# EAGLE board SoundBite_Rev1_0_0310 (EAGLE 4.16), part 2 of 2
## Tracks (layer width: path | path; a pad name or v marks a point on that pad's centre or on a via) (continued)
MISO/SDA  (via drill 0.6) (continued)
  Bottom 0.254: v82.04,25.53 82.04,25.91 80.39,27.56 80.39,39.75 78.87,41.27 78.87,41.66 79.88,42.67 79.88,44.58 78.49,45.97 v78.49,46.99 | v40.77,11.05 38.35,11.05 36.2,13.21 36.2,18.67 39.88,22.35 39.88,22.99 v42.29,25.4 42.29,27.69 44.83,30.23 44.83,62.87 46.48,64.52 v46.48,65.28 | v43.81,74.17 42.67,75.31 42.67,86.23 40.77,88.14 35.43,88.14 34.92,88.65 SW2.8
  pour Bottom (isolate 0.508, rank 2, no thermals): 34.04,90.42 34.04,92.33 arc-90 34.92,93.22 arc-90 35.81,92.33 35.81,90.42 arc-90 34.92,89.53 arc-90
MODA  (via drill 0.6)
  Top 0.254: v49.78,65.41 49.78,67.56 46.23,71.12 46.23,75.44 46.99,76.2 46.99,83.06 47.75,83.82 47.75,93.47 45.09,96.14 45.09,97.28
  Top 0.381: U1.51 64.83,52.01 64.26,52.58 v64.26,52.83
  Top 1.27: 45.09,97.28 SW2.1
  Bottom 0.254: v64.26,52.83 63.5,53.59 63.5,57.78 62.48,58.8 56.01,58.8 53.34,61.47 52.32,61.47 49.78,64.01 v49.78,65.41
  pour Bottom (isolate 0.254, rank 2, no thermals): 45.97,100.58 arc90 45.47,101.09 44.7,101.09 arc90 44.2,100.58 44.2,98.3 arc90 44.7,97.79 45.47,97.79 arc90 45.97,98.3
MODB  (via drill 0.6)
  Top 0.254: v50.67,64.52 49.4,64.52 48.9,65.02 48.9,67.69 45.72,70.87 45.72,75.69 46.48,76.45 46.48,83.31 47.24,84.07 47.24,93.22 44.7,95.76 44.07,95.76 42.55,97.28
  Top 0.381: v64.39,54.23 64.39,54.04 65.48,52.95 U1.50
  Top 1.27: 42.55,97.28 SW2.2
  Bottom 0.254: v64.39,54.23 64.39,57.66 62.74,59.31 56.26,59.31 53.59,61.98 52.58,61.98 50.67,63.88 v50.67,64.52
  pour Bottom (isolate 0.254, rank 2, no thermals): 42.16,97.79 arc-90 41.66,98.3 41.66,100.58 arc-90 42.16,101.09 42.93,101.09 arc-90 43.43,100.58 43.43,98.3 arc-90 42.93,97.79
MODC  (via drill 0.6)
  Top 0.254: v51.56,65.41 51.56,64.01 51.05,63.5 49.66,63.5 48.39,64.77 48.39,67.44 45.21,70.61 45.21,75.95 45.97,76.71 45.97,83.57 46.74,84.33 46.74,92.96 44.45,95.25 42.04,95.25 40.01,97.28
  Top 0.381: U1.49 66.13,53.76 v65.66,54.23
  Top 1.27: 40.01,97.28 SW2.3
  Bottom 0.254: v65.66,54.23 65.02,54.86 65.02,57.78 62.99,59.82 56.52,59.82 53.85,62.48 52.83,62.48 51.56,63.75 v51.56,65.41
  pour Bottom (isolate 0.254, rank 2, no thermals): 39.62,97.79 arc-90 39.12,98.3 39.12,100.58 arc-90 39.62,101.09 40.39,101.09 arc-90 40.89,100.58 40.89,98.3 arc-90 40.39,97.79
MODD  (via drill 0.6)
  Top 0.254: v52.45,64.39 52.45,63.63 51.82,62.99 49.4,62.99 47.88,64.52 47.88,67.18 44.7,70.36 44.7,76.2 45.47,76.96 45.47,83.82 46.23,84.58 46.23,92.71 44.2,94.74 40.01,94.74 37.47,97.28
  Top 0.381: U1.48 66.78,54.51 65.91,55.37 v65.91,55.5
  Top 1.27: 37.47,97.28 SW2.4
  Bottom 0.254: v65.91,55.5 65.91,57.78 63.37,60.33 56.77,60.33 54.1,62.99 53.09,62.99 52.45,63.63 v52.45,64.39
  pour Bottom (isolate 0.254, rank 2, no thermals): 37.08,97.79 arc-90 36.58,98.3 36.58,100.58 arc-90 37.08,101.09 37.85,101.09 arc-90 38.35,100.58 38.35,98.3 arc-90 37.85,97.79
MOSI  (via drill 0.6)
  Top 0.254: U1.34 76.32,45.07 77.34,46.1 v79.76,46.1 | v17.4,9.02 16.51,8.13 16.51,3.68 17.27,2.92 R63.2 | v41.78,6.35 41.78,9.91 42.16,10.29 42.16,13.97 50.04,21.84 81.41,21.84 v84.2,24.64
  Top 1.016: v17.4,9.02 R114.P$1
  Bottom 0.254: v17.4,9.02 20.45,5.97 41.4,5.97 v41.78,6.35 | v79.76,46.1 80.39,45.47 80.39,43.18 81.41,42.16 81.41,28.7 84.2,25.91 v84.2,24.64
N$1
  Top 0.381: U5.40 88.48,46.19 R22.2
N$2
  Top 0.254: 43.56,47.12 R20.1
  Top 0.508: U12.1 43.56,47.12 | Q1.1 38.35,54.86 C30.1
  Top 1.27: R20.1 43.43,49.78 Q1.1
N$3
  Top 1.016: C31.1 R21.1
  Top 1.27: R21.1 37.59,50.8 Q1.2
N$4
  Top 0.508: U12.2 42.29,46.35 41.78,46.86 41.78,47.12 R20.2 41.02,46.61 U12.3
  Top 1.27: R20.2 R21.2
N$5
  Top 0.254: 92.45,56.26 C37.+
  Top 0.381: U5.31 95.39,55.49 C38.1
  Top 0.406: C38.1 92.45,56.26
N$6
  Top 0.381: U5.28 97.79,54.23 96.65,55.37 R23.1
N$7
  Top 0.254: 98.59,56.17 R24.1
  Top 0.381: U5.27 98.59,56.17
N$8
  Top 0.254: 57.12,69.24 C44.1
  Top 0.356: 57.12,69.24 U2.18
  Top 1.016: C43.+ C44.1
N$9
  Top 0.254: 73.63,69.24 C46.1
  Top 0.356: 73.63,69.24 U3.18 | C45.+ C46.1
N$10
  Top 0.254: C48.1 90.14,69.24 | C47.+
  Top 0.356: 90.14,69.24 U4.18 | C47.+ C48.1
N$11
  Top 0.508: C55.- 49.78,87.68 51.99,85.47 R30.2
  Top 1.27: R30.2 R31.2
N$12
  Top 0.254: 101.79,56.2 R25.1
  Top 0.381: U5.23 101.79,56.2
N$13  (via drill 0.6)
  Top 1.27: R50.1 92.71,13.21 91.06,11.56 v91.06,8.26
  Bottom 1.27: v91.06,8.26 90.42,7.62 85.84,7.62 J8.3
N$14
  Top 0.254: U1.76 55.1,39.22 R58.2
N$15
  Top 0.508: R8.2 4.95,5.71 6.86,5.71 LED13.C
N$16
  Top 0.254: 62.61,87.88 C56.-
  Top 0.508: 62.61,87.88 60.71,85.98 60.2,85.98 R32.2
  Top 1.27: R33.2 R32.2
N$17  (via drill 0.6)
  Top 1.27: v59.69,89.92 R32.1
  Bottom 1.27: J3.1 53.33,89.92 v59.69,89.92
N$18
  Top 0.254: C57.- 65.66,87.88
  Top 0.508: R35.2 R34.2 68.07,85.98 67.56,85.98 65.66,87.88
N$19  (via drill 0.6)
  Top 1.27: R34.1 68.58,89.53 | 68.58,89.53 68.58,89.54 | v70.23,93.98 70.23,91.19 68.58,89.53
  Bottom 1.27: J5.3 75.45,93.98 v70.23,93.98
N$20
  Top 0.254: 79.12,87.88 C58.-
  Top 0.508: 79.12,87.88 77.22,85.98 76.71,85.98 R36.2
  Top 1.27: R37.2 R36.2
N$21  (via drill 0.6)
  Top 1.27: v76.2,89.92 R36.1
  Bottom 1.27: J5.1 69.84,89.92 v76.2,89.92
N$22
  Top 0.254: R59.2 53.34,35.5
  Top 0.381: 53.34,35.5 53.53,35.5 54.48,36.45 54.48,37.59 55.47,38.57 U1.77
N$23
  Top 0.254: C59.- 82.17,87.88
  Top 0.508: 82.17,87.88 84.07,85.98 84.58,85.98 R38.2
  Top 1.27: R38.2 R39.2
N$24  (via drill 0.6)
  Top 1.27: R38.1 85.09,89.53 86.74,91.19 v86.74,93.98
  Bottom 1.27: J7.3 91.96,93.98 v86.74,93.98
N$25
  Top 0.254: 95.63,87.88 C60.-
  Top 0.508: 95.63,87.88 93.73,85.98 93.22,85.98 R40.2
  Top 1.27: R41.2 R40.2
N$26  (via drill 0.6)
  Top 1.27: v92.71,89.92 R40.1
  Bottom 1.27: J7.1 86.35,89.92 v92.71,89.92
N$27
  Top 0.381: U1.78 55.83,37.92 55.12,37.21 55.12,35.94 54.48,35.31 54.48,34.42 53.47,33.4 R60.2
N$28
  Top 1.27: R9.1 LED1.A
N$29
  Top 0.254: C61.-
  Top 0.508: R42.2 60.07,15.49 61.09,14.48 61.09,14.1 61.59,13.59 C61.-
  Top 1.27: R43.2 R42.2
N$30  (via drill 0.6)
  Top 1.27: R42.1 59.69,13.21 58.04,11.56 v58.04,8.26
  Bottom 1.27: v58.04,8.26 57.4,7.62 52.82,7.62 J4.3
N$31
  Top 0.508: C62.- 50.16,13.59 50.67,14.1 50.67,14.48 51.69,15.49 R44.2
  Top 1.27: R44.2 R45.2
N$32  (via drill 0.6)
  Top 1.27: v52.07,11.68 R44.1
  Bottom 1.27: J4.1 58.43,11.68 v52.07,11.68
N$33
  Top 1.27: R10.1 LED2.A
N$34
  Top 0.254: C63.-
  Top 0.508: R46.2 76.58,15.49 77.6,14.48 77.6,14.1 78.11,13.59 C63.-
  Top 1.27: R47.2 R46.2
N$35
  Top 1.27: R11.1 LED3.A
N$36
  Top 0.254: R3.2 20.83,86.87 19.05,85.09 R2.1
N$37  (via drill 0.6)
  Top 1.27: R46.1 76.2,13.07 74.55,11.42 v74.55,8.26
  Bottom 1.27: v74.55,8.26 73.91,7.62 69.33,7.62 J6.3
N$38
  Top 0.254: 23.5,54.99 23.52,55.02 VR3(3.3V).1 | R7.2 20.83,54.74 19.05,52.96 R6.1
  Top 1.27: R7.2 23.5,54.99
N$39
  Top 0.508: C64.- 66.67,13.59 67.18,14.1 67.18,14.48 68.2,15.49 R48.2
  Top 1.27: R48.2 R49.2
N$40  (via drill 0.6)
  Top 1.27: v68.58,11.68 R48.1
  Bottom 1.27: J6.1 74.94,11.68 v68.58,11.68
N$41
  Top 0.254: C65.-
  Top 0.508: C65.- 94.61,13.59 94.11,14.1 94.11,14.48 93.09,15.49 R50.2
  Top 1.27: R51.2 R50.2
N$43
  Top 0.508: C66.- 83.31,13.59 83.69,13.97 83.69,14.48 84.71,15.49 R52.2
  Top 1.27: R52.2 R53.2
N$44  (via drill 0.6)
  Top 1.27: v85.09,11.68 R52.1
  Bottom 1.27: J8.1 91.45,11.68 v85.09,11.68
N$45
  Top 0.381: U1.4 60.93,32.73 59.44,31.24 57.91,31.24 57.28,30.61 56.64,30.61 R54.2
N$46
  Top 0.381: U1.5 61.58,32.37 59.82,30.61 58.67,30.61 R55.2
N$47
  Top 0.381: U1.6 62.23,32.13 R56.2
N$48
  Top 0.381: U1.7 62.88,30.75 R57.2
N$49
  Top 0.254: R61.2 55.12,33.15 55.12,34.8 55.88,35.56 57.91,35.56 58.8,36.45 58.8,36.96 58.48,37.27 U1.79
N$50
  Top 0.254: U1.10 64.83,34.09 64.77,34.04 64.77,32 65.66,31.11 R62.2
N$51
  Top 1.016: R65.1 SW2.12
N$52
  Top 0.254: R64.1
  Top 0.381: U1.46 68.08,54.74 68.45,55.12 68.45,56.52 R64.1
N$53
  Top 1.016: R66.1 SW2.11
N$54
  Top 1.016: R67.1 SW2.10
N$55
  Top 1.016: R68.1 SW2.9
N$56
  Top 0.254: R4.1 19.05,66.67 20.83,68.45 R5.2 | 23.55,68.71 VR2(1.25V).1
  Top 1.27: R5.2 23.55,68.71
N$57
  Top 0.508: R69.1 SW1.8
N$58
  Top 0.508: R70.1 SW1.7
N$59
  Top 0.508: R71.1 SW1.6
N$60
  Top 0.508: R72.1 SW1.5
N$61
  Top 0.508: R73.1 SW1.4
N$62
  Top 0.508: R74.1 SW1.3
N$63
  Top 0.508: R75.1 SW1.2
N$64
  Top 0.508: R76.1 SW1.1
N$65
  Top 0.254: U1.54 62.88,54.75 63.75,55.63 R77.1
N$66
  Top 0.254: 62.23,56.39 R78.1
  Top 0.381: U1.55 62.23,56.39
N$67
  Top 0.381: U1.56 61.58,55.01 R79.1
N$68
  Top 0.381: U1.57 60.93,53.63 R80.1
N$69
  Top 0.381: U1.58 60.28,52.25 R81.1
N$70
  Top 0.254: R82.1 54.61,55.88 55.37,55.88 55.44,55.82
  Top 0.381: U1.59 59.63,51.63 55.44,55.82
N$71
  Top 0.254: 54.93,55.18 54.86,55.24 54.51,55.24 54,55.75 52.7,55.75 R83.1
  Top 0.381: U1.60 58.98,51.13 54.93,55.18
N$72
  Top 0.381: U1.61 57.4,51.56 54.48,54.48 R84.1
N$73
  Top 0.254: U1.62 56.45,48.32 56.26,48.51 56.26,50.93 54.74,52.45 R85.1
N$74
  Top 0.254: U1.63 56.34,47.67 55.75,48.26 55.75,49.91 55.24,50.42 R86.1
N$75
  Top 0.254: U1.66 54.73,45.72 54.48,45.97 R87.1
N$76
  Top 0.254: U1.67 56.4,45.07 56.26,45.21 54.61,45.21 R88.1
N$77
  Top 0.254: 42.04,82.68 U6.3 43.43,82.68 44.07,82.04 44.07,79.38 43.31,78.61 43.31,77.47 42.42,76.58 R91.2
  Top 0.508: R90.1 41.91,76.33 R91.2
N$78
  Top 0.254: 106.05,96.27 106.07,96.24 J1.3
  Top 1.27: J1.3 106.68,95.61 106.68,89.53 | 106.68,89.53 R93.1 108.33,84.07 109.22,83.19 C73.- | 106.68,89.53 JP1.4
N$79  (via drill 0.6)
  Top 0.254: C72.- 96.65,81.92
  Top 0.508: J1.2 99.06,89.36 R92.1 98.68,83.69 97.79,83.69 96.52,82.42 C72.- | v109.6,94.13 111.12,92.61 111.12,88.27 JP1.2
  Bottom 0.508: J1.2 101.77,92.08 102.92,92.08 104.95,94.11 109.6,94.11 v109.6,94.13
N$80
  Top 0.254: R97.2 105.41,16.51 103.89,14.99 103.89,13.11
  Top 1.27: J2.2 103.89,13.11
N$81  (via drill 0.6)
  Top 0.254: 114.05,61.98 U14.6
  Top 0.381: U14.6 112.14,61.98 111.51,62.61 v111.51,65.66
  Top 0.508: R99.1 114.94,59.82 114.94,61.09 114.05,61.98 | JP1.1 112.39,84.96 111,83.57 v111,80.9
  Top 1.27: JP1.1 JP1.3
  Bottom 0.508: v111.51,65.66 111.51,80.39 v111,80.9
N$82  (via drill 0.6)
  Top 0.508: C79.+ 111.89,57.41 112.14,57.66 R99.2 v110.87,60.07 | U14.2 106.93,63.25 105.03,65.15 v105.03,69.85
  Bottom 0.508: v110.87,60.07 110.87,64.01 v105.03,69.85
N$83
  Top 0.508: J1.6 101.6,86.49 R94.2
N$84
  Top 0.254: C79.- 108.58,56.26
  Top 0.508: 108.58,56.26 107.7,57.15 R100.1
N$85
  Top 1.27: R96.1 R98.1 100.97,20.57 100.97,22.73 C76.-
N$86
  Top 0.508: C75.- 104.52,20.83 R97.1
  Top 1.27: R97.1 R95.1
N$87
  Top 0.508: J2.3 99.67,15.98 100.33,16.64 R98.2
N$88
  Top 0.254: C81.- 109.98,73.02 110.87,73.91 110.87,75.82 R102.2
  Top 0.508: U14.3 109.22,61.98 109.73,62.48 109.73,64.9 108.2,66.42 106.55,66.42 105.92,67.06 105.92,69.09 106.3,69.47 R101.1 107.44,70.48 108.58,71.63 C81.-
N$89
  Top 0.508: C81.+ 108.58,76.2 111,78.61 111.51,78.61 R103.2 112.14,83.44 114.3,85.6 114.3,93.98 MIC.P+
N$90  (via drill 0.6)
  Top 0.254: U7.6 21.47,24.25 v21.21,24.51
  Top 0.508: C87.P$1 v21.21,20.19
  Bottom 0.508: v21.21,24.51 22.23,23.5 22.23,20.95 21.46,20.19 v21.21,20.19
N$91
  Top 0.508: USB.D- 10.12,23.66 10.79,22.99 13.97,22.99 15.24,24.26 R105.P$2
  Top 1.27: R105.P$2 15.49,26.04 C86.P$1
N$92  (via drill 0.6)
  Top 0.254: U7.8 22.23,23.25 21.21,22.23 v21.21,21.59
  Top 0.762: R105.P$1 17.91,24.89 v18.8,24.89
  Bottom 0.508: v21.21,21.59 18.8,24 v18.8,24.89
N$93
  Top 0.254: U7.7 21.97,23.75 19.94,21.72 R107.P$1
  Top 0.508: R106.P$1 17.78,21.72 R107.P$1
N$94
  Top 0.254: U7.44 26.81,32.89
  Top 1.016: Q2.1 26.81,32.89 26.8,32.89 26.16,33.53 C84.P$1
N$95
  Top 0.254: U7.43 27.31,30.36 27.57,30.61
  Top 0.508: 27.57,30.61 29.34,32.38 29.34,36.45 Q2.2
  Top 1.016: Q2.2 26.42,39.37 C83.P$1
N$96
  Top 0.508: U8.4 5.02,36.64 4.7,36.96 R109.P$1 R108.P$2
N$97
  Top 0.254: U7.2 22.26,26.25 22.1,26.42 22.1,27.05 22.61,27.56 22.61,30.48 20.19,32.89 11.18,32.89 9.53,34.54 7.75,34.54 7.11,35.18 U8.3
  Top 0.508: U8.3 7.11,38.35 6.35,39.12 R108.P$1
N$98
  Top 0.254: U7.48 24.15,28.3 23.75,28.7 23.75,30.86 20.7,33.91 11.68,33.91 9.65,35.94 U8.1 9.65,36.7
N$99
  Top 0.254: U8.2 8.38,35.31 8.64,35.05 9.78,35.05 11.43,33.4 20.45,33.4 23.24,30.61 23.24,26.77 U7.1
N$100  (via drill 0.6)
  Top 0.254: U7.46 25.81,30.07 v25.27,30.61
  Top 0.508: C88.P$1 19.68,29.46 | 19.68,29.46 R104.P$1 | 19.68,29.46 v20.95,29.46
  Bottom 0.508: v20.95,29.46 24.13,29.46 v25.27,30.61
N$101
  Top 0.508: USB.VBUS 10.85,24.46
  Top 1.016: 10.85,24.46 11.86,24.46 12.19,24.13 L3.1
N$102  (via drill 0.6)
  Top 0.635: 20.19,36.45 U15.6
  Top 1.27: v17.91,41.91 v19.18,41.91 20.32,41.91 20.57,41.66 C92.P$2 20.57,38.48 U15.8 U15.7 20.19,36.45
  Bottom 1.27: JP3.3 1.65,92.96 1.65,49.66 9.4,41.91 v19.18,41.91
N$103
  Top 0.508: USB.D+ 9.78,22.86 10.79,21.84 C85.P$1 15.11,21.84 R106.P$2
N$104
  Top 1.27: PWR_JACK.- 5.21,80.64 PWR_JACK.-- 8.38,76.58 4.19,72.39 G1.AC1
N$105
  Top 1.27: G1.AC2 3.17,67.31 11.56,75.69 PWR_JACK.+
N$106
  Top 0.254: U7.5 22.24,24.75 21.59,25.4 20.57,25.4 19.68,24.51 R107.P$2
N$107
  Top 0.508: U9.18 R126.P$2
N$108
  Top 0.508: U9.16 R127.P$2
N$109
  Top 0.254: 8.13,17.91 8.12,17.91 USB.GND4 8,17.91 | USB.GND2 8,27.81 | USB.GND1
  Top 0.508: USB.GND3 2.66,17.91 1.02,19.56 1.02,26.29 2.54,27.81 USB.GND1
  Top 1.27: USB.GND3 USB.GND4 | 8,17.91 C93.2 | USB.GND1 8,27.81
N$110  (via drill 0.6)
  Top 0.254: U11.4 36.64,57.34 35.94,56.64 33.66,56.64 33.02,57.28 33.02,63.75 34.54,65.28 42.8,65.28 43.31,65.79 43.31,67.06 42.04,68.33 v42.04,72.9
  Top 1.016: v25.65,93.09 25.65,91.19 SW3.P$1
  Bottom 0.254: v42.04,72.9 42.04,73.79 41.66,74.17 41.66,85.72 40.26,87.12 32.89,87.12 26.92,93.09 v25.65,93.09
N$111
  Top 0.508: U9.14 R128.P$2
N$112
  Top 0.508: U9.7 21.21,6.35 R113.P$2
N$113  (via drill 0.6)
  Top 0.254: 58.85,34.54 58.98,34.54 U1.1
  Top 0.508: 58.85,34.54 56.77,34.54 v56.39,34.16
  Bottom 0.508: v56.39,34.16 57.28,34.16 58.8,32.64 PC7.P$1
N$114
  Top 0.254: R114.P$2 20.7,9.02 20.83,8.89
  Top 0.508: 20.83,8.89 U9.5
N$115
  Top 0.508: R115.P$2 U9.3
N$116
  Top 0.254: R121.P$1 20.7,5.08
  Top 0.508: 20.7,5.08 U9.8
N$117
  Top 1.27: R12.1 LED4.A
N$118
  Top 1.27: R13.1 LED5.A
N$119
  Top 1.27: R14.1 LED6.A
N$120
  Top 0.254: 36.32,2.54 R124.P$1
  Top 0.508: U9.11 36.32,2.54
N$121
  Top 0.254: 47.5,25.91 R116.P$1
  Top 0.508: U10.2 46.61,25.02 47.5,25.91
N$122
  Top 0.508: U10.7 46.23,31.37 46.99,32.13 R117.P$1
N$123
  Top 0.508: U10.14 37.97,26.29 R122.P$2
N$124
  Top 1.27: R15.1 LED7.A
N$125
  Top 1.27: R16.1 LED8.A
N$126
  Top 1.27: R17.1 LED9.A
N$127
  Top 1.27: LED10.A R143.1
N$128
  Top 1.27: LED11.A R144.1
N$129
  Bottom 1.27: CON1.6 PAD3.P$1
N$130
  Top 1.27: LED12.A R145.1
N$131
  Bottom 1.27: CON1.4 PAD1.P$1
N$132
  Bottom 1.27: PAD4.P$1 CON1.7
N$133
  Bottom 1.27: PAD2.P$1 CON1.5
N$134  (via drill 0.6)
  Top 1.27: R30.1 52.32,89.28 53.72,90.68 v53.72,93.98
  Bottom 1.27: J3.3 58.93,93.98 v53.72,93.98
N$727
  Top 0.254: 23.55,84.84 VR1(5V).1 | R2.2 20.83,84.58 19.05,82.8 R1.1 19.05,82.42
  Top 1.27: R2.2 23.55,84.84
OUT_0_SPDIF  (via drill 0.6)
  Top 0.254: v105.66,46.1 105.58,46.19
  Top 0.381: 105.58,46.19 U5.16
  Bottom 0.508: v105.66,46.1 105.66,26.67 109.22,23.11 109.22,20.57 105.54,16.89 103.38,16.89 J2.8
OUT_1_L  (via drill 0.6)
  Top 0.254: C62.+ 49.15,16.26 49.66,16.76
  Top 0.356: U2.19 57.77,70.88 58.04,70.61 59.82,70.61 v60.2,70.99
  Top 0.508: 49.66,16.76 v61.21,16.76
  Bottom 0.254: v60.2,70.99 62.23,68.96 83.44,68.96 84.2,68.2 84.2,40.64 91.69,33.15 91.69,19.56 90.81,18.67 63.12,18.67 v61.21,16.76
OUT_1_R  (via drill 0.6)
  Top 0.356: U2.20 60.66,71.93 v61.59,70.99
  Top 0.508: C61.+ 62.61,16 63.12,15.49 v64.14,15.49
  Bottom 0.254: v64.14,15.49 63.25,16.38 63.25,17.14 64.26,18.16 91.06,18.16 92.2,19.3 92.2,33.4 84.71,40.89 84.71,68.45 83.69,69.47 63.12,69.47 v61.59,70.99
OUT_2_L  (via drill 0.6)
  Top 0.356: U3.19 74.28,70.88 74.55,70.61 75.56,70.61 v75.95,70.99
  Top 0.508: C64.+ 65.66,16.76 v64.14,16.76
  Bottom 0.254: v64.14,16.76 65.02,17.65 91.31,17.65 92.71,19.05 92.71,33.66 85.22,41.15 85.22,68.71 83.95,69.98 76.96,69.98 v75.95,70.99
OUT_2_R  (via drill 0.6)
  Top 0.356: U3.20 76.41,71.93 v77.34,70.99
  Top 0.508: C63.+ 79.5,16.76 v80.64,16.76
  Bottom 0.254: v80.64,16.76 91.19,16.76 93.22,18.8 93.22,33.91 85.72,41.4 85.72,68.96 83.69,70.99 v77.34,70.99
OUT_3_L  (via drill 0.6)
  Top 0.254: 82.17,16 C66.+
  Top 0.356: U4.19 90.79,70.88 91.06,70.61 92.08,70.61 v92.46,70.99
  Top 0.508: 82.17,16 81.66,15.49 v80.64,15.49
  Bottom 0.254: v80.64,15.49 90.68,15.49 93.73,18.54 93.73,34.16 86.23,41.66 86.23,68.96 88.27,70.99 v92.46,70.99
OUT_3_R  (via drill 0.6)
  Top 0.254: C65.+ 95.63,16
  Top 0.356: U4.20 92.92,71.93 93.73,71.12 v93.73,70.99
  Top 0.508: 95.63,16 96.14,15.49 v97.16,15.49
  Bottom 0.254: v97.16,15.49 94.23,18.41 94.23,34.42 86.74,41.91 86.74,68.71 88.01,69.98 92.96,69.98 93.73,70.74 v93.73,70.99
OUT_O_L  (via drill 0.6)
  Top 0.254: v107.31,21.46 v107.32,21.47
  Top 0.381: U5.32 94.59,54.38 v94.11,54.86
  Top 1.27: v107.32,21.47 C75.+
  Bottom 0.254: v107.31,21.46 106.3,22.48 95.89,22.48 95.25,23.11 95.25,34.92 87.76,42.42 87.76,48.51 v94.11,54.86
OUT_O_R  (via drill 0.6)
  Top 0.254: v98.42,21.46 v98.42,21.47
  Top 0.356: U5.33 93.19,52.99 92.71,53.47 v92.71,54.86
  Top 1.27: v98.42,21.47 C76.+
  Bottom 0.254: v92.71,54.86 87.25,49.4 87.25,42.16 94.74,34.67 94.74,22.23 95.5,21.46 v98.42,21.46
PDN  (via drill 0.6)
  Top 0.254: U2.17 56.47,72.98 56.64,73.15 63.12,73.15 67.56,68.71 71.12,68.71 72.98,70.57 U3.17 72.98,72.98 73.15,73.15 79.63,73.15 84.07,68.71 87.63,68.71 89.49,70.57 U4.17 | U11.1 34.1,59.24 33.66,59.69 33.66,61.85 R125.1 34.8,63.25 36.32,64.77 43.94,64.77 | U13.2 45.59,63.75 44.96,64.39 44.32,64.39 43.94,64.77 | v43.05,68.71 43.94,67.82 43.94,64.77
  Top 0.356: U4.17 89.49,72.86 89.79,73.15 92.96,73.15 94.74,71.37 94.74,63.37 v94.36,62.99 | U2.17 56.47,70.7 55.75,69.98 v55.75,68.07
  Top 0.381: U5.5 96.99,39.2 v96.52,38.73
  Bottom 0.254: v55.75,68.07 54.48,69.34 43.69,69.34 v43.05,68.71
  Bottom 0.381: v94.36,62.99 96.27,64.9 99.69,64.9 103.25,61.34 103.25,53.98 97.16,47.88 97.16,39.37 v96.52,38.73
PWREN#  (via drill 0.6)
  Top 0.254: U7.41 28.31,29.84 v28.83,30.35
  Top 0.508: U15.4 15.37,34.67 15.62,34.92 v17.65,34.92
  Bottom 0.508: v28.83,30.35 27.3,30.35 25.65,32 20.57,32 v17.65,34.92
RESET  (via drill 0.6)
  Top 0.254: R141.1 18.67,18.8 21.84,18.8 23.24,20.19 v23.24,20.45 23.24,21.23 U7.12 | U13.1 46.86,63.63 v45.21,65.28
  Bottom 0.254: v23.24,20.45 30.35,20.45 30.73,20.83 32.13,20.83 42.55,31.24 42.55,31.75 44.32,33.53 44.32,63.5 45.21,64.39 v45.21,65.28
SCK  (via drill 0.6)
  Top 0.254: v85.98,24.64 85.98,24.26 82.55,20.83 50.55,20.83 43.18,13.46 43.18,9.78 42.8,9.4 42.8,7.87 v43.81,6.86 | v43.81,72.9 43.81,70.36 47.37,66.8 47.37,64.26 48.01,63.63 v48.01,62.61
  Top 0.381: U1.36 75.97,46.37 77.09,47.5 v77.34,47.5 | R122.P$1 37.21,27.69 36.2,26.67 36.2,23.62 v39.37,20.45
  Top 0.508: R122.P$1 R123.2
  Top 1.016: v17.4,11.43 R115.P$1
  Bottom 0.254: v77.34,47.5 78.11,48.26 80.14,48.26 81.41,46.99 81.41,43.81 82.42,42.8 82.42,29.59 85.98,26.04 v85.98,24.64 | v17.4,11.43 17.4,10.29 21.21,6.48 40.26,6.48 41.27,7.49 43.18,7.49 v43.81,6.86 43.81,7.75 44.58,8.51 44.58,9.27 41.02,12.83 37.34,12.83 36.7,13.46 36.7,17.78 v39.37,20.45 40.39,21.46 40.39,22.23 43.18,25.02 43.18,27.81 45.34,29.97 45.34,59.94 v48.01,62.61 | v43.81,72.9 42.16,74.55 42.16,85.98 40.51,87.63 33.15,87.63 32.38,88.39 SW2.7
  pour Bottom (isolate 0.508, rank 2, no thermals): 32.38,89.53 arc-90 31.5,90.42 31.5,92.33 arc-90 32.38,93.22 arc-90 33.27,92.33 33.27,90.42 arc-90
SCLK  (via drill 0.6)
  Top 0.254: U4.16 88.84,70.68 87.38,69.22 84.33,69.22 79.88,73.66 72.9,73.66 72.33,73.1 U3.16 72.33,70.68 70.87,69.22 67.82,69.22 63.37,73.66 56.39,73.66 55.82,73.1 U2.16 55.82,70.94 54.86,69.98 54.86,64.64 55.5,64.01 55.5,62.99 v52.58,60.07 | R58.1 50.29,38.73 50.29,42.55 49.4,43.43 49.4,46.35 50.42,47.37 50.42,49.28 R86.2
  Top 0.356: U4.16 88.84,73.1 89.53,73.79 93.22,73.79 95.38,71.63 95.38,61.59 96.52,60.45 97.28,60.45 98.68,59.05 R24.2
  Top 0.508: R86.2 51.56,51.44 | 51.56,51.44 R85.2 | R59.1 R58.1 | 51.56,51.44 v50.29,51.44
  Bottom 0.381: v50.29,51.44 50.29,57.78 v52.58,60.07
SDI/I2C  (via drill 0.6)
  Top 0.254: U7.20 28.31,16.25 28.07,16 27.18,16 25.91,14.73 24.13,14.73 | LED12.C 8.76,9.4 8.76,13.59 9.14,13.97 21.59,13.97 22.35,14.73 24.13,14.73 | 24.13,14.73 v24.13,15.11
  Top 0.508: R132.1 4.45,8.26 6.86,8.26 LED12.C | v37.97,23.24 38.48,23.75 U10.16 U10.1 | v43.43,31.37 43.43,32 44.07,32.64 U10.8
  Bottom 0.254: v24.13,15.11 24.51,14.73 25.91,14.73 27.69,16.51 31.24,16.51 v37.97,23.24 37.97,24 38.23,24.26 38.23,26.16 v43.43,31.37
SDI/SPI  (via drill 0.6)
  Top 0.254: LED11.C 8.26,11.43 8.26,13.97 8.76,14.48 21.34,14.48 22.86,16 24.64,16 25.15,16.51 26.16,16.51 26.92,17.27 v26.92,17.91 26.81,18.02 U7.17
  Top 0.508: R139.1 4.45,10.79 6.86,10.79 LED11.C | v31.24,17.91 31.24,13.59 32.13,12.7 U9.19
  Bottom 0.508: v26.92,17.91 v31.24,17.91
SS  (via drill 0.6)
  Top 0.254: v42.8,5.46 42.8,6.6 42.29,7.11 42.29,9.65 42.67,10.03 42.67,13.72 50.29,21.34 82.17,21.34 85.09,24.26 v85.09,25.53
  Top 0.381: U1.37 75.47,47.02 76.96,48.51 78.61,48.51 v79.76,47.37
  Top 1.016: v17.4,6.99 R113.P$1
  Bottom 0.254: v17.4,6.99 18.92,5.46 v42.8,5.46 | v79.76,47.37 80.9,46.23 80.9,43.43 81.92,42.42 81.92,28.96 85.09,25.78 v85.09,25.53
SYSCLK  (via drill 0.6)
  Top 0.381: U5.21 105.05,50.19 105.28,50.42 105.28,51.44 104.14,52.58 v103.38,52.58 | v71.25,55.5 68.73,52.98 U1.45 68.73,49.55 68.2,49.02 v65.15,49.02 | v73.28,58.42 v88.65,58.42
  Top 0.508: v47.24,46.23 44.07,43.05 40.39,43.05 39.75,43.69 U12.4
  Bottom 0.254: v88.65,58.42 88.39,58.67
  Bottom 0.381: v103.38,52.58 103.89,53.09 103.89,62.1 100.46,65.53 95.5,65.53 92.08,62.1 89.03,62.1 88.39,61.47 88.39,58.67 | v71.25,55.5 71.25,56.39 v73.28,58.42 | v65.15,49.02 63.5,47.37 48.39,47.37 v47.24,46.23
TCK  (via drill 0.6)
  Top 0.254: R126.P$1 38.86,11.94 38.86,14.48 48.9,24.51 78.74,24.51 v78.99,24.77
  Top 0.381: U1.32 77.05,43.77 v77.34,44.07
  Bottom 0.254: v78.99,24.77 78.87,24.89 78.87,38.73 77.34,40.26 v77.34,44.07
TCK/SK/SCC  (via drill 0.6)
  Top 0.254: U9.17 33.66,10.16 | 30.1,12.7 30.1,14.22 30.31,14.44 U7.24 31.13,19.7 v31.37,19.94 | 38.99,25.02 U10.15
  Top 0.381: 38.99,25.02 38.48,24.51 v37.21,24.51
  Top 0.508: U9.2 30.1,12.7 32.64,10.16 U9.17
  Bottom 0.508: v37.21,24.51 32.64,19.94 v31.37,19.94
TDI  (via drill 0.6)
  Top 0.254: R127.P$1 39.37,9.91 39.37,14.22 49.02,23.88 79.38,23.88 80.01,24.51 v80.01,25.53
  Top 0.381: U1.31 78.18,43.12 v78.49,43.43
  Bottom 0.254: v80.01,25.53 79.38,26.16 79.38,39.12 77.85,40.64 77.85,42.8 v78.49,43.43
TDI/DO  (via drill 0.6)
  Top 0.254: U9.15 33.66,7.62 | U7.23 29.81,14.82 29.46,14.48 28.96,14.48 v28.32,13.84 | v41.27,26.29 U10.3
  Top 0.508: U9.4 24.51,10.16 25.91,11.56 v28.32,11.56 28.7,11.56 32.64,7.62 U9.15
  Bottom 0.254: v28.32,13.84 28.32,14.86 28.96,15.49 32.26,15.49 39.37,22.61 39.37,24.38 v41.27,26.29
  Bottom 0.508: v28.32,11.56 v28.32,13.84
TDO  (via drill 0.6)
  Top 0.254: v83.31,25.53 83.31,25.02 80.64,22.35 49.78,22.35 41.66,14.22 41.66,10.54 41.27,10.16 41.27,7.24 40.89,6.86 40.89,5.46 v41.78,4.57
  Top 0.381: U1.30 79.45,42.47 v80.52,41.4
  Top 1.016: v17.4,4.95 R121.P$2
  Bottom 0.254: v17.4,4.95 41.4,4.95 v41.78,4.57 | v80.52,41.4 80.52,40.51 80.9,40.13 80.9,27.94 v83.31,25.53
TDO/DI  (via drill 0.6)
  Top 0.254: U7.22 29.31,15.21 29.08,14.99 28.19,14.99 v27.05,13.84
  Top 0.508: v43.43,30.1 U10.6 | U9.9 27.05,3.81 | 27.05,3.81 v27.05,9.02 | 27.05,3.81 U9.12
  Bottom 0.254: v27.05,13.84 27.05,14.73 28.32,16 32,16 38.86,22.86 38.86,25.53 v43.43,30.1
  Bottom 0.508: v27.05,9.02 v27.05,13.84
TMS  (via drill 0.6)
  Top 0.254: U1.33 76.43,44.42 77.22,45.21 v77.98,45.21 | R128.P$1 39.88,7.87 39.88,13.97 49.28,23.37 79.63,23.37 v81.03,24.77
  Bottom 0.254: v81.03,24.77 81.03,26.04 79.88,27.18 79.88,39.37 78.36,40.89 78.36,41.91 79.38,42.93 79.38,43.81 v77.98,45.21
TMS/CS  (via drill 0.6)
  Top 0.254: U9.13 33.66,5.08 | v25.78,13.84 27.43,15.49 28.57,15.49 28.81,15.73 U7.21
  Top 0.508: U9.6 25.27,7.62 25.78,8.13 v25.78,9.78 26.42,10.41 28.7,10.41 31.75,7.37 31.75,5.97 32.64,5.08 U9.13
  Bottom 0.508: v25.78,9.78 v25.78,13.84
TRST
  Top 0.254: U7.11 22.26,21.75 22.1,21.59 22.1,19.81 21.59,19.3 18.41,19.3 17.91,18.8 16.64,18.8 R142.1
V+  (via drill 0.6)
  Top 0.254: 4.32,91.44 4.29,91.42 C29.+ | C80.+ 113.92,74.95 R102.1 | C33.+ 87.88,52.33 | U5.35 90.32,50.19 90.3,50.16 | C34.1 87.91,50.19
  Top 0.381: U5.36 90.56,49.39 90.3,49.66 90.3,50.16 | 87.91,50.19 U5.35
  Top 0.508: R102.1 R103.1 | 87.88,52.33 C34.1 | U14.7 114.55,63.25 115.06,63.75 115.06,68.96 113.03,70.99
  Top 0.762: v89.28,52.7 C33.+ | v100.97,73.53 100.97,68.2 v100.58,67.82
  Top 1.016: C78.1 v109.47,70.99 113.03,70.99 C80.+
  Top 1.27: R19.2 L2.1 5.84,91.44 | 4.32,91.44 5.84,91.44 | 5.84,91.44 JP3.2
  Bottom 0.762: v89.28,52.7 87.5,54.48 87.5,62.1 93.22,67.82 v100.58,67.82
  Bottom 1.016: JP3.2 5.84,99.44 6.86,100.46 24.38,100.46 29.21,95.63 46.35,95.63 48.39,93.6 48.39,89.41 49.53,88.27 93.98,88.27 96.39,85.85 99.31,85.85 100.08,85.09 | v109.47,70.99 106.93,73.53 v100.97,73.53 100.08,74.42 100.08,85.09 | 100.08,85.09 112.65,85.09 117.86,90.3 CON1.1
VCC  (via drill 0.6)
  Top 0.254: C16.1 53.59,39.75 56.26,39.75 56.38,39.87 U1.75 | C21.+ | v74.68,49.53 74.68,49.02 73.98,48.32 U1.39 | C67.+ | U1.17 69.38,33.88 69.72,33.53 69.72,32 70.23,31.5 C13.1 | U1.25 73.81,39.22 74.04,38.99 74.04,38.73 74.55,38.23 74.8,38.23 C14.1 75.31,37.47 | 38.23,76.2 R90.2 38.23,76.07 | 19.94,16 R140.2 20.19,16.51 24.38,16.51 25.4,17.53 C90.P$2 25.31,17.87 U7.14 | U7.31 33.9,24.25 C91.P$2 | R111.1 46.23,26.92 43.69,26.92 | 11.43,44.07 11.68,43.81 | R125.2 C99.1 36.96,60.58 36.96,59.27 U11.5 | C97.1 49.02,58.93 49.4,59.31 | 60.71,39.88 60.7,39.87 | U12.14 43.56,38.48 | v10.67,16 10.16,16
  Top 0.381: U1.64 55.85,47.02 54.86,48.01 54.86,48.39 | 54.86,48.39 v54.86,49.4 | U1.17 69.38,36.41 v67.94,37.85 60.71,37.85 60.28,37.42 U1.3 | 54.86,48.39 C15.1
  Top 0.406: U1.64 59.53,47.02 60.71,45.85 60.71,39.88 60.71,37.85 | U1.41 73.03,50.55 C68.1 | U1.3 60.28,33.1 59.82,32.64 C12.1 | 60.7,39.87 U1.75
  Top 0.508: C32.1 46.1,39.24 45.31,38.46 U12.14 43.56,36.96 42.93,36.32 39.88,36.32 39.37,35.81 C96.P$1 39.54,34.37 U10.9 | U13.14 48.11,56.74 v48.39,57.02 48.77,57.4 C97.1 | 74.68,51.18 C68.1 | 74.68,51.18 C69.1 | U10.9 38.48,32.64 R123.1 37.59,31.37 36.2,31.37 35.31,30.48 35.31,25.27 34.42,24.38 C91.P$2 34.04,21.84 37.97,17.91 v37.97,13.97 | U10.9 40.89,32.64 41.4,32.13 41.4,28.19 | 41.4,28.19 40.77,27.56 U10.13 | 41.4,28.19 42.67,26.92 43.69,26.92 | J1.8 104.14,86.49 C74.1 | v74.68,49.53 74.68,51.18
  Top 0.61: C71.1 37.92,78.36 37.92,79.68 37.47,80.14 U6.8
  Top 0.635: C94.P$1 U9.20
  Top 0.762: J2.7 C77.1 | R133.2 2.67,14.48 4.19,16 v10.67,16 v14.35,16 R142.2 | v37.97,13.97 C94.P$1 | v37.85,63.25 36.83,63.25 R125.2 | v95,83.19 95.38,83.57 96.39,83.57 97.54,84.71 v97.54,88.52 | 75.31,37.47 75.31,36.58 75.82,36.07 v76.71,36.07 | v42.29,66.17 40.77,67.69 40.77,74.8 | 40.77,74.8 39.12,74.8 38.23,75.69 R90.2 | 40.77,74.8 42.8,74.8 v43.69,75.69 | v116.2,30.86 122.43,30.86 124.21,32.64 SW1.9
  Top 1.016: L1.2 C22.1 | v15.75,12.57 R143.2 | SW1.9 SW1.10 SW1.11 SW1.12 SW1.13 SW1.14 SW1.15 SW1.16 124.84,53.47 126.11,54.74 126.11,86.49 CON1.2 | v56.77,64.01 v63.5,64.01
  Top 1.27: R142.2 R141.2 R140.2 | R133.2 R139.2 R132.2 | C69.1 77.72,51.18 C67.+ | R90.2 C71.1 | R143.2 R144.2 R145.2 | 11.68,43.81 C21.+ | 11.43,44.07 v11.43,45.21 L1.2
  Bottom 0.508: v54.86,49.4 50.42,49.4 48.39,51.44 v48.39,57.02
  Bottom 0.762: v43.69,75.69 43.69,77.47 43.43,77.72 43.43,85.22 44.07,85.85 92.33,85.85 v95,83.19 | v97.54,88.52 104.87,88.52 | J2.7 104.37,15.88 106.17,15.88 110.87,20.57 110.87,25.53 v116.2,30.86
  Bottom 1.016: v14.35,16 15.75,14.61 v15.75,12.57 15.75,4.83 17.02,3.56 25.4,3.56 26.29,2.67 42.04,2.67 45.72,6.35 45.72,10.29 42.04,13.97 v37.97,13.97 | v76.71,36.07 76.33,36.07 73.41,38.99 | 73.41,38.99 73.41,48.26 v74.68,49.53 74.68,58.93 73.91,59.69 69.47,59.69 65.15,64.01 v63.5,64.01 | 37.85,63.5 15.62,63.5 13.72,61.59 13.72,56.13 16.26,53.59 16.26,51.44 11.43,46.61 v11.43,45.21 12.32,44.32 19.05,44.32 20.57,42.8 20.57,41.15 15.62,36.2 15.62,26.8 10.67,21.84 v10.67,16 | 73.41,38.99 69.09,38.99 v67.94,37.85 | 37.85,63.5 v37.85,63.25 | 37.85,63.5 39.62,63.5 v42.29,66.17 44.07,66.17 45.09,67.18 52.96,67.18 56.13,64.01 v56.77,64.01 | J1.8 104.87,88.52 104.87,90.3 107.28,92.71 121.67,92.71 122.3,92.08 CON1.2
VCCINT
  Top 0.254: 17.14,30.35 17.27,30.48 | 4.06,33.02 3.94,32.89 C95.P$2 | U8.6 7.11,32.26 | R104.P$2 17.91,31.62 18.29,32 20.32,32 21.97,30.35 21.97,27.81 21.46,27.3 21.46,26.29 22.23,25.53 | U7.42 27.81,27.05 27.81,26.67 26.42,25.27 24.77,25.27 | U8.8 9.65,30.48 | 24.77,25.27 24.74,25.25 U7.4 22.5,25.25 22.23,25.53 | 22.23,25.53 22.45,25.75 U7.3 24.41,25.75 24.64,25.53 24.64,25.27 24.77,25.27
  Top 0.508: C95.P$2 3.56,34.04 R109.P$2 | 7.11,33.53 U8.6
  Top 0.635: U15.3 13.84,36.58 U15.2
  Top 1.016: 17.27,30.48 R104.P$2 | 11.18,40.26 6.73,40.26 6.22,40.77 2.54,40.77 1.91,40.13 1.91,34.42 2.29,34.04 3.56,34.04 5.33,34.04 5.84,33.53 7.11,33.53 9.27,33.53 9.65,33.15 9.65,31.5 | 11.18,40.26 C98.P$2 | 11.18,40.26 11.18,37.08 11.68,36.58 13.84,36.58 14.22,36.58 | 9.65,31.5 U8.8 | 9.65,31.5 11.18,31.5 | 11.18,31.5 11.18,27.69 L3.2 | 11.18,31.5 12.83,31.5 12.95,31.37 C82.+ 14.6,31.5 C89.P$1
  Top 1.27: C89.P$1 17.14,30.35
VCCIO  (via drill 0.6)
  Top 0.254: C27.+ | 107.95,43.43 C39.+ | 90.3,46.99 90.17,46.86 | 83.57,46.86 C35.+ | 96.9,46.99 96.99,47.08
  Top 0.381: 101.73,46.99 101.73,46.23 102.56,45.39 U5.15 104.98,45.39 105.28,45.09 106.43,45.09 C40.1 | 101.73,46.99 U5.17 | 90.3,46.99 U5.39 96.9,46.99 101.73,46.99 | 87.88,46.86 C36.1 | 90.17,46.86 87.88,46.86 | 87.88,46.86 83.57,46.86
  Top 0.406: 96.99,47.08 U5.29
  Top 0.508: 107.95,43.43 v107.06,44.32 C40.1
  Top 1.27: R19.1 v11.56,88.9 12.57,88.9 | 12.57,88.9 C27.+ | 12.57,88.9 12.57,88.78 C28.1
  Bottom 1.016: v11.56,88.9 11.56,98.17 12.57,99.19 23.75,99.19 28.57,94.36 45.72,94.36 47.12,92.96 47.12,88.65 48.77,87 93.34,87 98.55,81.79 98.55,73.91 108.84,63.63 108.84,46.1 v107.06,44.32
VDD  (via drill 0.6)
  Top 0.254: 53.85,42.42 C20.1 | 53.85,42.42 53.9,42.47 | 53.85,42.42 54.36,42.93 55.12,42.93 55.5,42.55 56.39,42.55 56.46,42.47 U1.71 58.86,42.47 v58.93,42.55 | 63.53,29.57 C17.1 | 20.83,66.17 R4.2 | VR2(1.25V).2 26.67,66.42 | 26.67,66.42 29.72,66.42 | 79.12,40.89 C18.1 79.5,40.26 | U1.52 64.18,51.52 63.37,52.32 63.37,54.48 C19.1 | 26.67,66.42 26.67,61.85 26.16,61.85 25.86,61.55 D2.2 | v63.5,36.58 63.53,36.55
  Top 0.305: U1.29 78.19,41.82 79.12,40.89
  Top 0.381: U1.8 63.53,29.57 | C70.1 71.75,56.9 72.26,56.39 72.26,55.12 69.38,52.23 U1.44 69.38,48.8 68.58,48.01 64.77,48.01 64.18,48.6 U1.52
  Top 0.406: 63.53,36.55 U1.8
  Top 0.508: R129.2 C7.1 16.76,65.41 17.4,64.77 v20.83,64.77 | 20.83,65.53 20.83,65.41
  Top 0.762: 79.5,40.26 81.03,40.26 81.66,40.89 81.66,42.04 80.9,42.8 v80.9,49.66
  Top 1.016: 20.83,66.17 20.83,65.53 v20.83,64.77 | R4.2 VR2(1.25V).2 | v56.77,65.28 v61.98,65.28 | 29.72,66.42 VR2(1.25V).4 | C70.1 69.98,56.9 v69.98,55.75
  Top 1.27: 26.67,66.42 26.67,69.09 23.88,71.88 C6.+
  Bottom 1.016: v56.77,65.28 53.59,68.45 44.58,68.45 43.56,67.44 41.78,67.44 39.12,64.77 v20.83,64.77 | v63.5,36.58 62.48,36.58 60.33,38.73 60.33,41.91 59.69,42.55 v58.93,42.55 58.93,43.94 59.56,44.58 65.15,44.58 69.98,49.4 v69.98,55.75 69.98,57.28 64.52,62.74 62.61,62.74 61.98,63.37 v61.98,65.28 65.79,65.28 69.98,61.09 74.68,61.09 75.95,59.82 75.95,51.18 77.47,49.66 v80.9,49.66
  pour Top (isolate 0.508, rank 2): 31.75,61.59 31.75,71.75 22.86,71.75 22.86,61.59
  pour Top (isolate 0.508, rank 2, no thermals): 27.94,69.22 31.75,69.22 31.75,67.31 31.75,63.5 27.3,63.5 27.3,69.22
VEE  (via drill 0.6)
  Top 0.254: 20.83,52.45 R6.2 | 11.56,52.83 C10.+ 11.43,52.68 | 16.76,52.83 C11.1 | VR3(3.3V).2 25.91,52.7 | 25.91,52.7 VR3(3.3V).4 | D2.1 25.86,52.75 25.91,52.7 | v73.03,80.01 72.98,79.97 | v89.53,80.01 89.49,79.97 | v56.52,80.01 56.47,79.97
  Top 0.356: C49.1 56.9,80.39 v56.52,80.01 | 72.98,79.97 U3.4 | C51.1 73.41,80.39 v73.03,80.01 | 89.49,79.97 U4.4 | C53.1 89.92,80.39 v89.53,80.01 | 56.47,79.97 U2.4
  Top 1.27: R6.2 VR3(3.3V).2 | C10.+ v13.72,52.83 v14.99,52.83 16.76,52.83 | R18.2 L1.1 11.43,52.68 | 20.83,52.45 20.83,51.56 20.19,50.93 17.91,50.93 16.89,51.94 C11.1
  Bottom 0.635: 73.03,78.87 v73.03,80.01 | 73.03,78.87 89.15,78.87 89.53,79.25 v89.53,80.01 | 49.4,79.76 50.8,81.15 52.07,81.15 54.36,78.87 56.52,78.87 | 56.52,78.87 73.03,78.87 | 56.52,78.87 v56.52,80.01
  Bottom 1.016: v14.99,52.83 v13.72,52.83 12.45,54.1 12.45,62.1 16.38,66.04 38.61,66.04 42.93,70.36 48.01,70.36 49.4,71.75 49.4,79.76
  other vias: 25.4,41.91 29.21,41.91 33.02,41.91 33.02,44.45 29.21,44.45 24.13,44.45 24.13,48.26 26.67,48.26 29.21,48.26 31.75,48.26 31.75,52.7 31.75,57.15 29.21,57.15 26.67,57.15 24.13,57.15 26.67,54.61 26.67,50.8 29.21,60.33 31.75,60.33
  pour Top (isolate 0.508, rank 3): 22.86,60.71 22.86,41.27 30.48,41.27 31.11,40.64 31.11,27.3 35.31,27.3 35.31,42.8 32,45.85 32,60.71
  pour Bottom (isolate 0.508, rank 3): 22.86,62.36 34.67,62.36 34.67,27.94 31.11,27.94 31.11,41.27 22.86,41.27
  pour Top (isolate 0.508, rank 2, no thermals): 27.94,55.24 27.94,50.16 31.75,50.16 31.75,55.24
VIN  (via drill 0.6)
  Top 0.254: 23.55,80.26 VR1(5V).3 23.62,80.19 | G1.+ 11.43,67.31
  Top 1.27: 23.55,80.26 C1.1 | v11.81,69.98 v11.81,68.71 G1.+ 9.4,67.31 8.76,66.67 C2.+ | 23.62,78.74 23.62,80.19 | 23.62,78.74 D1.1 | v24.26,78.74 23.62,78.74 | 23.62,78.74 v22.99,78.74
  Bottom 1.27: v11.81,68.71 v11.81,69.98 20.57,78.74 v24.26,78.74
VPP  (via drill 0.6)
  Top 0.254: C23.+ 8.64,43.81 | v55.12,80.01 55.17,79.95 | v71.63,80.01 71.68,79.95 | v88.14,80.01 88.19,79.95
  Top 0.356: U4.5 U4.6 88.19,79.95 | U3.5 U3.6 71.68,79.95 | U2.5 U2.6 55.17,79.95 | C50.1 54.74,80.39 v55.12,80.01 | C52.1 71.25,80.39 v71.63,80.01 | C54.1 87.76,80.39 v88.14,80.01
  Top 0.381: U5.19 106.73,48.59 C42.1 | v48.01,74.93 R28.2
  Top 0.508: C42.1 107.06,50.04 107.06,50.8 C41.+ 107.44,50.8 v107.44,51.94
  Top 1.27: C24.1 R18.1 v8.89,45.21 8.89,44.07 8.64,43.81
  Bottom 0.635: 48.01,80.01 50.04,82.04 53.09,82.04 v55.12,80.01 55.12,80.39 55.88,81.15 57.28,81.15 58.67,79.76 71.37,79.76 v71.63,80.01 71.63,80.39 72.39,81.15 73.66,81.15 75.06,79.76 87.88,79.76 v88.14,80.01 88.14,80.39 88.9,81.15 90.17,81.15 91.06,80.26
  Bottom 0.762: v107.44,51.94 107.44,62.74 91.06,79.12 91.06,80.26
  Bottom 1.016: 48.01,80.01 v48.01,74.93 48.01,72.52 47.12,71.63 42.42,71.63 38.1,67.31 15.88,67.31 11.18,62.61 11.18,50.16 8.89,47.88 v8.89,45.21

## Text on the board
tPlace: 2 | 1 | 3
tNames: + | + | RESET | + | + | + | + | + | + | + | + | + | + | + | + | + | + | + | + | Rev 1.0 | + | + | + | + | + | + | + | + | + | + | + | + | + | + | Symphony | + | + | SoundBite | LEDx | 10:JTAG | 11:SPI | + | + | + | + | + | + | 12:I2C | 13:PWR
bNames: S | S | M | M | M | M | C | D | O | O | O | O | L | A | D | D | D | D | JP3: Power Source Select | D | C | B | A | 1-2: External, 6VAC/9VDC via PWR_JACK | 2-3: USB Power (May impact AK4584 performance) | NONE: No jumper if regulated 5V is supplied via CON1 | SW2: Boot Mode Select | CON1: Expansion Header | JP1: Microphone Select | Pos Signal For Pos.1-4: | +3.3V | 2 | +5V | 1 | 1-2: Route output to J1 Left | ON = Logic 0 | PAD1 | 4 | GND | 3 | MODA | 1 | 3-4: Route output to J1 Right | OFF = Logic 1 | MODB | 2 | PAD3 | 6 | PAD2 | 5 | For Example, | 110110 (654321) | GPLED8 | 8 | PAD4 | 7 | MODC | 3 | Audio I/O (All Stereo) | is Mode 9 with | BOOT EE enabled | MODD | 4 | GPLED7 | 10 | GPLED0 | 9 | J1: Combo Optical/Analog input | GPLED6 | 12 | GPLED1 | 11 | BOOT EE SDA enable | 5 | J2: Combo Optical/Analog output | BOOT EE SCL enable | 6 | GPLED5 | 14 | GPLED2 | 13 | J3/J5/J7: Analog input | GPLED4 | 16 | GPLED3 | 15 | J2/J4/J6: Analog output | GPSW7 | 18 | GPSW0 | 17 | GPSW6 | 20 | GPSW1 | 19 | LED1-9: General Purpose LEDs | GPSW5 | 22 | GPSW2 | 21 | SW1: General Purpose Switches | DSP Pin | Signal | ID | GPSW4 | 24 | GPSW3 | 23 | Pos Signal DSP Pin | LED1 GPLED0 PF7 | GND | 26 | GND | 25 | PF0 | GPSW0 | 1 | LED2 GPLED1 PF8 | PF1 | GPSW1 | 2 | LED3 GPLED2 PF9 | PF2 | GPSW2 | 3 | LED4 GPLED3 PF10 | PF3 | GPSW3 | 4 | LED5 GPLED4 TIO0/PB0 | PF4 | GPSW4 | 5 | LED6 GPLED5 TIO1/PB1 | PF5 | GPSW5 | 6 | LED7 GPLED6 PC2 | PD0 | GPSW6 | 7 | LED8 GPLED7 PC5 | PD1 | GPSW7 | 8 | LED9 GPLED8 PC6 | SW3: System/Board RESET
